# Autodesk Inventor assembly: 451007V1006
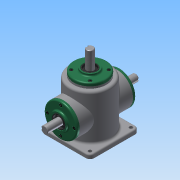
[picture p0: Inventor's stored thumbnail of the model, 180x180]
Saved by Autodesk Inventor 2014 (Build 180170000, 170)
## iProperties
Created: 2015-10
Part Number: 451007V1006
Document SubType Name: Assembly
Designer: SDA
Author: SDA
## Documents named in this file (14)
- C:\Users\SDA\Desktop\451007V1006\451007V1006.iam
- C:\Users\SDA\Desktop\451007V1006\본체.ipt
- C:\Users\SDA\Desktop\451007V1006\메인 베벨기어.ipt
- C:\Users\SDA\Desktop\451007V1006\메인 축.ipt
- 메인 축.ipt
- C:\Users\SDA\Desktop\451007V1006\베어링 6203.ipt
- C:\Users\SDA\Desktop\451007V1006\오일실.ipt
- C:\Users\SDA\Desktop\451007V1006\커버.ipt
- C:\Users\SDA\Desktop\451007V1006\키 5x5.ipt
- C:\Users\SDA\Desktop\451007V1006\서브 베벨기어.ipt
- C:\Users\SDA\Desktop\451007V1006\서브 축.ipt
- 서브 축.ipt
- C:\Users\SDA\Desktop\451007V1006\키 4x4.ipt
- C:\Users\SDA\Desktop\451007V1006\M4.ipt
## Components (12 placed, 1 different names)
1. M4:1 — 각도:2
2. M4:4
3. M4:5
4. M4:6
5. M4:2 — 각도:3
6. M4:7
7. M4:8
8. M4:9
9. M4:3 — 각도:4
10. M4:10
11. M4:11
12. M4:12
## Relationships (3: Angle 3)
- 각도:2 [Angle]: M4:1
- 각도:3 [Angle]: M4:2
- 각도:4 [Angle]: M4:3
